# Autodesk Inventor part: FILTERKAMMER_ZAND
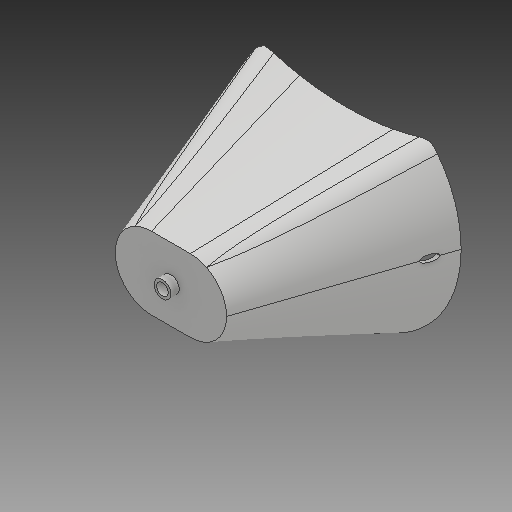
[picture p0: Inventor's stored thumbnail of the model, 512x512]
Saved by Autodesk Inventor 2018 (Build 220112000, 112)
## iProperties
Created: 2019-01
Part Number: FILTERKAMMER_ZAND
Material: Polypropylene (PP)
Document SubType Name: Modeling
Designer: zand
Density: 0.902188 g/cm^3
Appearance: Vorgabe
Mass: 62.0798 g
Surface Area: 696.982 cm^2
Volume: 68.8102 cm^3
Author: zand
Revision Number: 10LAST_VERSION
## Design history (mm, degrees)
feature "Basis1"
node "Volumenkörper1"
